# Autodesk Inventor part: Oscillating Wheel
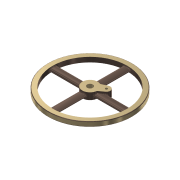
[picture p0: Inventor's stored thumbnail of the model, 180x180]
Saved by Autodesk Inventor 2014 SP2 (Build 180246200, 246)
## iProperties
Created: 2016-02
Part Number: Oscillating Wheel
Material: Steel, Cast
Document SubType Name: Modeling
Designer: User
Density: 7.85 g/cm^3
Appearance: Gunmetal - Antique Polished
Author: User
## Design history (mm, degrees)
sketch "Sketch1"
  geometry: C1 r 16 at (0, 0); C2 r 87.5 at (0, 0); C3 r 77.5 at (0, 0); 1 further point
  constraints: 3 centre point, 3 coincident
  dimensions: "d0" = 32 diameter of C1; "d1" = 175 diameter of C2; "d2" = 155 diameter of C3
extrude "Extrusion1" new body sketch "Sketch1" stored distance "d3" = 10; taper "d4" = 0 deg
extrude "Extrusion4" join sketch "Sketch1" stored distance "d39" = 14; taper "d40" = 0 deg
sketch "Sketch2" dims "d5" = 8, "d6" = 3
  geometry: 2 further points; 1 other entity
  constraints: 1 coincident, 2 other
extrude "Extrusion2" join sketch "Sketch2" stored distance "d7" = 10; taper "d8" = 0 deg
pattern_circular "Circular Pattern1" dims angle "d10" = 360 deg
fillet "Fillet1" dims "d12" = 2
hole "Hole1" diameter "d15" = 12; stored, may be unused: countersink angle "d19" = 90 deg, drill point angle "d21" = 118 deg; dims "d16" = 6, "d17" = 4, "d18" = 2, "d20" = 8, "d41" = 10, "d42" = 10
sketch "Sketch3"
  geometry: L1 (21.651, 12.5)-(0, 0); L2 (0, 0)-(16.583, 0); L3 (18.397, 19.808)-(6.621, 14.566); L4 (26.353, 6.028)-(15.925, -1.549); C1 r 6 at (0, 0) reference; C2 r 16 at (0, 0) reference; A1 r 8 centre (21.651, 12.5) between (26.353, 6.028) and (18.397, 19.808); A2 r 16 centre (0, 0) between (15.925, -1.549) and (6.621, 14.566)
  constraints: 8 end point, 4 point on circle, 2 centre point, 2 coincident, 2 tangent, 1 concentric, 1 equal length, 1 horizontal
  dimensions: "d22" = 30 deg angle of L2 L1; "d23" = 12 deg angle of L4 L3; "d24" = 25 distance of L1.start L1.end; "d25" = 8 radius of A1
extrude "Extrusion5" join sketch "Sketch3" distance "d45" = 14; taper "d46" = 0 deg
hole "Hole2" diameter "d31" = 5; stored, may be unused: countersink angle "d35" = 90 deg, drill point angle "d37" = 118 deg; dims "d32" = 6, "d33" = 4, "d34" = 2, "d36" = 8, "d47" = 10, "d48" = 10
fillet "Fillet3" dims "d38" = 1
fillet "Fillet4" dims "d49" = 2
body "Solid1"
